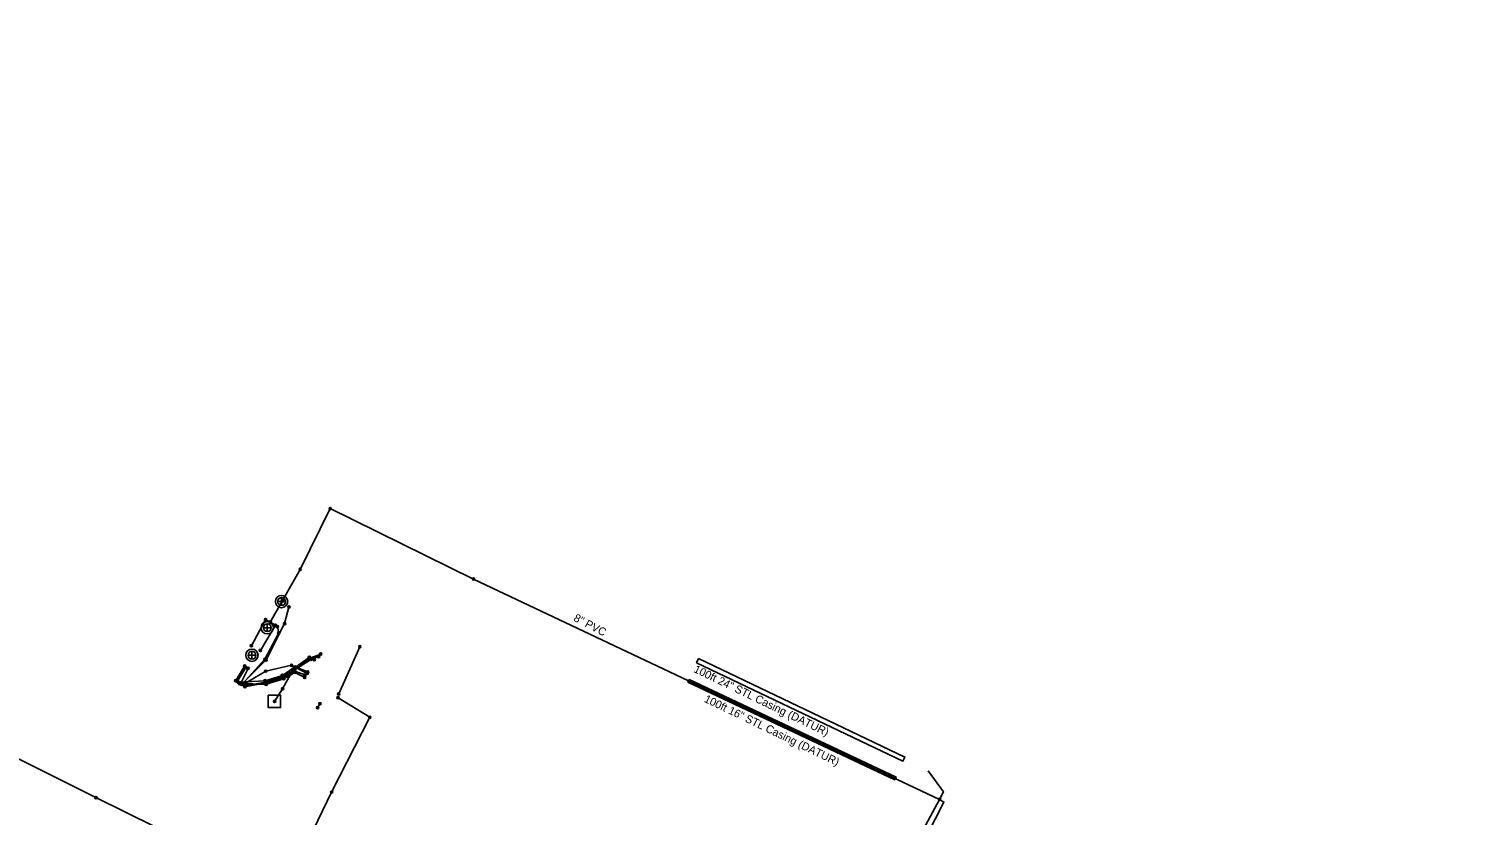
# Model space of a CAD drawing. Extents: x 2244485 to 2250986, y 199568 to 203007.
# Drawn here: x 2245302 to 2245934, y 202615 to 202958 of the extents above; entities that cross this region are included whole.
import ezdxf

# ---------------------------------------------------------------- set-up
doc = ezdxf.new("R2010")
doc.units = 0
for name, color, linetype in [('Default', 7, 'Continuous'), ('Exist Structure Minor Storm Sewer Line Text', 7, 'Continuous'), ('Exist Utilities Gas UG Line SUE LOS B', 7, 'Continuous'), ('Exist Utilities Other Pole With Base CELL', 7, 'Continuous'), ('Exist Utilities Power UG Cable SUE LOS B', 7, 'Continuous'), ('Exist Utilities Sanitary Sewer Forced Main SUE LOS B', 7, 'Continuous'), ('Exist Utilities Sanitary Sewer Forced Main SUE LOS B Text', 7, 'Continuous'), ('Exist Utilities Sanitary Sewer Forced Main SUE LOS C', 7, 'Continuous'), ('Exist Utilities Sanitary Sewer Manhole CELL', 7, 'Continuous')]:
    doc.layers.add(name, color=color, linetype=linetype)

# ---------------------------------------------------------------- blocks, each defined once
blk = doc.blocks.new('SurveyPointCell')
at = {"layer": 'Default'}
for p, q in [((-0.5, 0), (0.5, 0)), ((0, -0.5), (0, 0.5))]:
    blk.add_line(p, q, dxfattribs=at)
blk.add_circle((0, 0), 0.5, dxfattribs=at)

msp = doc.modelspace()

# ---------------------------------------------------------------- linework, layer by layer
at = {"layer": 'Exist Structure Minor Storm Sewer Line Text'}
for points in [[(2245594.92, 202683.06), (2245685.16, 202639.97), (2245684.3, 202638.17), (2245594.06, 202681.25)], [(2245590.87, 202673.97), (2245681.27, 202631.24), (2245680.7, 202630.03), (2245590.3, 202672.77)]]:
    msp.add_lwpolyline(points, close=True, dxfattribs=at)
at = {"layer": 'Exist Utilities Gas UG Line SUE LOS B'}
msp.add_lwpolyline([(2244658.96, 202958.49), (2244721.96, 202928.3), (2244863.47, 202856.19), (2244912.51, 202831.57), (2245070.07, 202752.33), (2245256.14, 202659.91), (2245331.4, 202622.29), (2245514.38, 202531.76), (2245606.53, 202488.05), (2245652.12, 202465.42), (2245827.69, 202375.08), (2246001.01, 202291.84), (2246162.3, 202211.17), (2246329.12, 202125.74), (2246513.99, 202036.93), (2246642.7, 201974.75), (2246734.96, 201930.33), (2246858.92, 201868.26), (2246999.42, 201799.12), (2247177.53, 201710.71), (2247331.7, 201633.3), (2247466.92, 201567.22), (2247602.4, 201501.88), (2247749.1, 201426.01)], dxfattribs=at)
at = {"layer": 'Exist Utilities Other Pole With Base CELL'}
msp.add_line((2245409.46, 202664.37), (2245409.46, 202664.37), dxfattribs=at)
msp.add_lwpolyline([(2245406.73, 202667.07), (2245412.13, 202667.07), (2245412.13, 202661.67), (2245406.73, 202661.67), (2245406.73, 202667.07)], dxfattribs=at)
msp.add_circle((2245409.46, 202664.37), 0.0707, dxfattribs=at)
at = {"layer": 'Exist Utilities Power UG Cable SUE LOS B'}
for points in [[(2245395.21, 202671.86), (2245405.81, 202682.51), (2245413.9, 202698.4), (2245415.78, 202705.61)], [(2245395.33, 202671.83), (2245405.27, 202682.8), (2245411.37, 202694.33), (2245410.76, 202697.01)], [(2245437.55, 202667.62), (2245446.8, 202688.25)], [(2245429.7, 202685.08), (2245424.88, 202683.28), (2245417.62, 202677.84), (2245413.1, 202675.46), (2245405.7, 202672.79), (2245396.4, 202671.15)], [(2245396.56, 202670.79), (2245405.7, 202672.45), (2245412.88, 202675.03), (2245417.7, 202677.69), (2245425.38, 202682.74), (2245428.75, 202683.95)], [(2245409.51, 202664.36), (2245413.06, 202669.87), (2245418, 202678.73), (2245424.77, 202683.65), (2245426.85, 202682.55)], [(2245392.56, 202673.48), (2245396.48, 202679.84)], [(2245396.95, 202679.11), (2245393.18, 202673.08)], [(2245393.77, 202672.75), (2245405.4, 202673.36), (2245412.94, 202675.71), (2245418.44, 202679.4), (2245424.01, 202677.24)], [(2245422.72, 202674.83), (2245418.33, 202677.06), (2245413.53, 202674.26), (2245405.87, 202671.92), (2245394.27, 202672.11)], [(2245394.73, 202672.37), (2245397.93, 202678.77)], [(2245395.22, 202671.88), (2245405.74, 202671.81), (2245413.6, 202674.81), (2245418.32, 202677.62), (2245422.7, 202675.95)], [(2245395.73, 202671.77), (2245405.63, 202677.57), (2245416.92, 202680.14), (2245423.82, 202676.57)], [(2245385.83, 202532.39), (2245408.84, 202572.53), (2245424.65, 202604.36), (2245434.48, 202624.66), (2245451.18, 202657.41), (2245437.28, 202665.96)], [(2245428.32, 202661.55), (2245429.35, 202663.31)]]:
    msp.add_lwpolyline(points, dxfattribs=at)
at = {"layer": 'Exist Utilities Sanitary Sewer Forced Main SUE LOS B'}
for points in [[(2245399.42, 202688.67), (2245405.58, 202700.11), (2245407.65, 202699.04), (2245412.89, 202708.23), (2245420.72, 202722.07), (2245433.83, 202748.71), (2245496.51, 202717.84), (2245700.29, 202621.51)], [(2245403.32, 202686.64), (2245409.93, 202697.68), (2245407.63, 202698.99)], [(2245613.42, 202432.81), (2245614.64, 202435.08), (2245625.47, 202460.2), (2245669.41, 202564.12), (2245700.29, 202621.51)]]:
    msp.add_lwpolyline(points, dxfattribs=at)
at = {"layer": 'Exist Utilities Sanitary Sewer Forced Main SUE LOS C'}
for points in [[(2245700.29, 202621.51), (2245702.01, 202624.74), (2245695.34, 202634.02)], [(2245629.15, 202398.66), (2245630.09, 202400.26), (2245625.31, 202402.84), (2245619.07, 202418.57), (2245613.43, 202429.99), (2245613.98, 202431.19), (2245637.91, 202484.15), (2245675.61, 202568.28), (2245702.23, 202620.32), (2245700.29, 202621.51)]]:
    msp.add_lwpolyline(points, dxfattribs=at)
at = {"layer": 'Exist Utilities Sanitary Sewer Manhole CELL'}
for points in [[(2245412.59, 202709.74), (2245412.59, 202706.32), (2245412.59, 202708.03), (2245414.31, 202708.03), (2245410.88, 202708.03)], [(2245406.35, 202698.31), (2245406.35, 202694.88), (2245406.35, 202696.6), (2245408.06, 202696.6), (2245404.63, 202696.6)], [(2245399.64, 202686.24), (2245399.64, 202682.82), (2245399.64, 202684.53), (2245401.35, 202684.53), (2245397.93, 202684.53)]]:
    msp.add_lwpolyline(points, dxfattribs=at)
for centre, radius in [((2245412.59, 202708.03), 2.69), ((2245412.59, 202708.03), 1.71), ((2245406.35, 202696.6), 2.69), ((2245406.35, 202696.6), 1.71), ((2245399.64, 202684.53), 2.69), ((2245399.64, 202684.53), 1.71)]:
    msp.add_circle(centre, radius, dxfattribs=at)

# ---------------------------------------------------------------- block references
at = {"layer": 'Default'}
for p in [(2245433.83, 202748.71), (2245420.72, 202722.07), (2245496.51, 202717.84), (2245412.89, 202708.23), (2245415.78, 202705.61), (2245405.58, 202700.11), (2245407.63, 202698.99), (2245407.65, 202699.04), (2245409.93, 202697.68), (2245410.76, 202697.01), (2245411.37, 202694.33), (2245413.9, 202698.4), (2245399.42, 202688.67), (2245403.32, 202686.64), (2245446.8, 202688.25), (2245405.27, 202682.8), (2245405.81, 202682.51), (2245416.92, 202680.14), (2245424.77, 202683.65), (2245424.88, 202683.28), (2245425.38, 202682.74), (2245426.85, 202682.55), (2245428.75, 202683.95), (2245429.7, 202685.08), (2245396.48, 202679.84), (2245396.95, 202679.11), (2245397.93, 202678.77), (2245405.63, 202677.57), (2245412.88, 202675.03), (2245412.94, 202675.71), (2245413.1, 202675.46), (2245413.53, 202674.26), (2245413.6, 202674.81), (2245417.62, 202677.84), (2245417.7, 202677.69), (2245418, 202678.73), (2245418.32, 202677.62), (2245418.33, 202677.06), (2245418.44, 202679.4), (2245422.7, 202675.95), (2245422.72, 202674.83), (2245423.82, 202676.57), (2245424.01, 202677.24), (2245392.56, 202673.48), (2245393.18, 202673.08), (2245393.77, 202672.75), (2245394.27, 202672.11), (2245394.73, 202672.37), (2245395.21, 202671.86), (2245395.22, 202671.88), (2245395.33, 202671.83), (2245395.73, 202671.77), (2245396.4, 202671.15), (2245396.56, 202670.79), (2245405.4, 202673.36), (2245405.7, 202672.79), (2245405.7, 202672.45), (2245405.74, 202671.81), (2245405.87, 202671.92), (2245413.06, 202669.87), (2245437.55, 202667.62), (2245409.51, 202664.36), (2245428.32, 202661.55), (2245429.35, 202663.31), (2245437.28, 202665.96), (2245451.18, 202657.41), (2245434.48, 202624.66), (2245331.4, 202622.29), (2245700.29, 202621.51)]:
    msp.add_blockref('SurveyPointCell', p, dxfattribs=at)

# ---------------------------------------------------------------- texts
at = {"layer": 'Exist Structure Minor Storm Sewer Line Text'}
for s, p in [('100ft 24" STL Casing (DATUR)', (2245592.48, 202677.3)), ('100ft 16" STL Casing (DATUR)', (2245597.04, 202664.29))]:
    msp.add_text(s, height=3.5, rotation=334.18334, dxfattribs=at).set_placement(p)
at = {"layer": 'Exist Utilities Sanitary Sewer Forced Main SUE LOS B Text'}
msp.add_text('8" PVC', height=3.5, rotation=332.41532, dxfattribs=at).set_placement((2245539.98, 202699.77))

doc.saveas('drawing.dxf')
